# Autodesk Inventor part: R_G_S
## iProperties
Shininess: 64.0
Length Units: 11269
Angle Units: 11279
Time Units: 11290
Mass Units: 11283
Length Display Precision: 3
Angle Display Precision: 2
Compacted: True
Part Number: R_G_S
Document SubType Name: Modeling
Created: 2004-08
Designer: John Blackburn
Manufacturer: Standard
Standards Organization: Custom
Density: 0.0
Volumn: 0.0
Area: 0.0
PropertySet Name: Model Information
Control State: 0
Master: False
Checked Out: False
Author: John Blackburn
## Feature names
1. Extrusion1
